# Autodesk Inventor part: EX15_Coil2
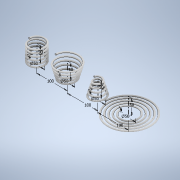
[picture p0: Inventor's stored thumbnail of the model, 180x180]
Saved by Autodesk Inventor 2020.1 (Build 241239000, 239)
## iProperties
Created: 2019-10
Part Number: EX15_Coil2
Material: Generic
Document SubType Name: Modeling
Designer: Synergysoft Dell02
Density: 1 g/cm^3
Appearance: Default
Author: Synergysoft Dell02
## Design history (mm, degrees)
sketch "Sketch1"
  geometry: L1 (0, 0)-(0, 50); L2 (-100, 0)-(-100, 50); L3 (100, 0)-(100, 50); L4 (200, 0)-(200, 50); C1 r 2.5 at (-25, 0); C2 r 2.5 at (-125, 0); C3 r 2.5 at (75, 0); C4 r 2.5 at (175, 0)
  constraints: 8 end point, 7 horizontal alignment, 4 centre point, 4 vertical
  dimensions: "d0" = 5 diameter of C1; "d1" = 50 distance of L1.start L1.end; "d2" = 50 diameter of C1.centre L1; "d3" = 5 diameter of C2; "d4" = 50 distance of L2.start L2.end; "d5" = 50 diameter of C2.centre L2; "d6" = 5 diameter of C3; "d7" = 50 distance of L3.start L3.end; "d8" = 50 diameter of C3.centre L3; "d9" = 5 diameter of C4; "d10" = 50 distance of L4.start L4.end; "d11" = 50 diameter of C4.centre L4; "d12" = 100 distance between parallel lines of L1 L2; "d13" = 100 distance between parallel lines of L3 L1; "d14" = 100 distance between parallel lines of L4 L3
coil "Coil1" pitch "d15" = 10; turns "d17" = 5; dims "d16" = 100, "d18" = 0, angle "d19" = 90 deg, angle "d20" = 90 deg, "d21" = 90 deg, "d22" = 90 deg
coil "Coil2" pitch "d23" = 10; turns "d25" = 5; dims "d24" = 50 (= d1), "d26" = 15 deg, angle "d27" = 90 deg, angle "d28" = 90 deg, "d29" = 0, "d30" = 0
coil "Coil3" pitch "d31" = 10; turns "d33" = 5; dims "d32" = 50 (= d7), "d34" = -15 deg, angle "d35" = 90 deg, angle "d36" = 90 deg, "d37" = 0, "d38" = 0
coil "Coil4" pitch "d39" = 10; turns "d41" = 5; dims "d40" = 50 (= d7), "d42" = -15 deg, angle "d43" = 90 deg, angle "d44" = 90 deg, "d45" = 0, "d46" = 0
body "Solid1"
